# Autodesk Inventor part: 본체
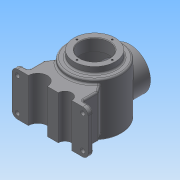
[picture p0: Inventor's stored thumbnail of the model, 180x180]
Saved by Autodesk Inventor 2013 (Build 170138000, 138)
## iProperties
Created: 2018-08
Part Number: 본체
Material: 일반
Document SubType Name: Modeling
Designer: Administrator
Density: 1 g/cm^3
Author: Administrator
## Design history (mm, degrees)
sketch "스케치1"
  geometry: L1 (0, 0)-(0, -108); L2 (0, 0)-(50, 0); L3 (50, 0)-(50, -96.671); L4 (50, -108)-(0, -108); L5 (50, -96.671)-(50, -108); A1 r 116 centre (0, 8) between (0, -108) and (50, -96.671)
  constraints: 10 end point, 4 perpendicular, 2 point on circle, 1 centre point, 1 tangent, 1 vertical
  dimensions: "d2" = 108 distance of L2.end L4.start; "d4" = 100 diameter of L3 L1; "d5" = 116 radius of A1
revolve "회전1" sketch "스케치1" stored, may be unused: angle "d6" = 90 deg
sketch "스케치2"
  geometry: C1 r 38 at (0, 0); 1 further point
  constraints: 1 centre point, 1 coincident
  dimensions: "d7" = 76 diameter of C1
extrude "돌출1" join sketch "스케치2" distance "d8" = 12; taper "d9" = 0 deg
sketch "스케치3"
  geometry: L1 (40, -90.163)-(40, -10); L2 (40, -10)-(0, -10); L3 (38, 12)-(-38, 12) reference; L4 (0, -10)-(0, -98); A1 r 116 centre (0, 8) between (-50, -96.671) and (50, -96.671) reference; A2 r 106 centre (0, 8) between (0, -98) and (40, -90.163); 2 further points
  constraints: 6 end point, 3 point on circle, 2 vertical alignment, 1 centre point, 1 vertical
  dimensions: "d10" = 10 radial gap between concentric circles of A1 A2; "d12" = 22 distance between parallel lines of L3 L2; "d13" = 80 diameter of L1 L4
revolve "회전2" sketch "스케치3" stored, may be unused: angle "d14" = 90 deg
hole "구멍1" diameter "d17" = 54; stored, may be unused: countersink angle "d21" = 90 deg, drill point angle "d23" = 0 deg; dims "d15" = 10, "d16" = 10, "d18" = 6, "d19" = 4, "d20" = 2, "d22" = 22
sketch "스케치4"
  geometry: 2 further points
  constraints: 1 vertical alignment
  dimensions: "d24" = 32.5 distance of point (0, 0) point (0, 32.5)
hole "구멍2" sketch "스케치4" at (0, 32.5) diameter "d25" = 3.242; stored, may be unused: countersink angle "d29" = 90 deg, drill point angle "d31" = 118 deg; dims "d26" = 8, "d27" = 4, "d28" = 2, "d30" = 10
node "작업 평면1"
sketch "스케치5"
  geometry: L1 (-50, -72)-(-70, -72); L2 (-70, -72)-(-70, -82); L3 (-70, -82)-(-40, -82); L4 (70, -82)-(70, -72); L5 (70, -72)-(50, -72); L6 (-5, -82)-(15, -82); L7 (40, -82)-(70, -82); L8 (-70, -72)-(-40.304, -29.59); L9 (70, -72)-(40.304, -29.59); L10 (-50, -72)-(-50, -43.437); L11 (50, -72)-(50, -43.437); L12 (-50, -43.437)-(-40.304, -29.59); L13 (50, -43.437)-(40.304, -29.59); A1 r 17.5 centre (-22.5, -82) between (-5, -82) and (-40, -82); A2 r 12.5 centre (27.5, -82) between (40, -82) and (15, -82); A3 r 50 centre (0, 0) between (-40.304, -29.59) and (40.304, -29.59); 3 further points
  constraints: 26 end point, 9 perpendicular, 6 point on circle, 5 point on line, 3 centre point, 2 collinear, 2 horizontal alignment, 1 coincident, 1 parallel, 3 other
  dimensions: "d41" = 17.5 radius of A1; "d42" = 12.5 radius of A2; "d43" = 22.5 horizontal distance of A1.centre point (0, 0); "d44" = 27.5 horizontal distance of A2.centre point (0, 0); "d45" = 10 distance of L1.end L2.end; "d46" = 140 distance of L2.end L4.start; "d47" = 70 distance from line of L4 point (0, 0); "d48" = 82 distance from line of L3 point (0, 0); "d55" = 20 distance of L4.end L5.end; "d114" = 35 deg angle of L8 L2; "d115" = 35 deg angle of L4 L9; "d116" = 20 distance of L1.start L1.end
extrude "돌출2" join sketch "스케치5" distance "d60" = 80; taper "d61" = 0 deg
fillet "모깎기1" dims "d62" = 10
sketch "스케치6"
  geometry: A1 r 10 centre (-10, 70) between (-10, 80) and (-20, 70) reference; A2 r 10 centre (-10, 10) between (-20, 10) and (-10, 0) reference; A3 r 10 centre (110, 10) between (110, 0) and (120, 10) reference; A4 r 10 centre (110, 70) between (120, 70) and (110, 80) reference; 5 further points
  constraints: 4 coincident
hole "구멍3" sketch "스케치6" at (-10, 70), (-10, 10), (110, 10), (110, 70) diameter "d63" = 8; stored, may be unused: countersink angle "d67" = 90 deg, drill point angle "d69" = 118 deg; dims "d64" = 8, "d65" = 4, "d66" = 2, "d68" = 10
node "작업 평면2"
sketch "스케치7"
  geometry: L1 (-10, 88)-(90, 88) reference; C1 r 38 at (40, 38); 1 further point
  constraints: 1 centre point, 1 vertical alignment
  dimensions: "d72" = 76 diameter of C1; "d74" = 50 distance from line of C1.centre L1
extrude "돌출3" join sketch "스케치7" stored distance "d75" = 80; taper "d76" = 0 deg
hole "구멍4" diameter "d79" = 54; stored, may be unused: countersink angle "d83" = 90 deg, drill point angle "d85" = 0 deg; dims "d80" = 8, "d81" = 4, "d82" = 2, "d84" = 10, "d86" = 10, "d87" = 10
sketch "스케치8"
  geometry: C1 r 27 at (0, 0) reference; 2 further points
  constraints: 1 vertical alignment
  dimensions: "d88" = 32.5 distance of C1.centre point (0, 32.5)
hole "구멍5" sketch "스케치8" at (0, 32.5) diameter "d89" = 3.242; stored, may be unused: countersink angle "d93" = 90 deg, drill point angle "d95" = 118 deg; dims "d90" = 8, "d91" = 4, "d92" = 2, "d94" = 10
node "작업 평면3"
sketch "스케치9"
  geometry: C1 r 32.5 at (0, 0); 1 further point
  constraints: 1 centre point, 1 coincident, 1 other
  dimensions: "d100" = 65 diameter of C1
feature "엠보싱1" sketch "스케치9" dims "d2" = 108, "d4" = 100, "d5" = 116, "d10" = 10, "d12" = 22, "d13" = 80, "d101" = 0.5, "d102" = 0
fillet "모깎기5" dims "d106" = 3
fillet "모깎기6" dims "d107" = 3
fillet "모깎기7" dims "d108" = 3
fillet "모깎기9" dims "d110" = 3
chamfer "모따기1" distance "d111" = 1; stored, may be unused: second distance "d112" = 2, angle "d113" = 45 deg
fillet "모깎기10" dims "d117" = 3
fillet "모깎기11" dims "d118" = 3
node "솔리드1"
pattern_circular "원형 패턴1" dims angle "d33" = 360 deg
pattern_circular "원형 패턴2" dims angle "d97" = 360 deg
other parameters: "d35" = -8, "d70" = -147, "d99" = -239
